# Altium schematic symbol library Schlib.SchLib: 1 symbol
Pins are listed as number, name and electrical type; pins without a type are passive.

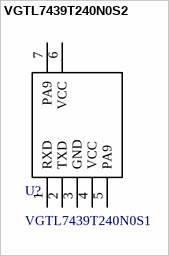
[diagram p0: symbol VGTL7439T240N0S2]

## VGTL7439T240N0S2
designator U?, comment VGTL7439T240N0S1
footprint G7439NS2_SMD
footprint G7439NS2_DIP
pins: 1 RXD, 2 TXD, 3 GND, 4 VCC, 5 PA9, 6 VCC, 7 PA9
